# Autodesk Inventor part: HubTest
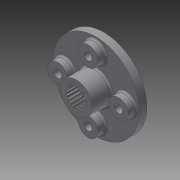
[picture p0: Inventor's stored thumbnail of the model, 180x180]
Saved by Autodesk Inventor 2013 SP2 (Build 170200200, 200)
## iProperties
Created: 2020-02
Part Number: HubTest
Material: Generic
Document SubType Name: Modeling
Designer: DELL
Density: 1 g/cm^3
Author: DELL
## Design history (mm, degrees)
sketch "Sketch1" dims "d2" = 4.61623
  geometry: C1 r 4 at (0, 0); C2 r 2.6 at (0, 0); A1 r 2.308 centre (0, 0) between (0.414, 2.271) and (0.308, 2.287); A2 r 1.037 centre (-0.708, 1.95) between (0.259, 2.327) and (0.255, 2.336); A3 r 0.063 centre (0.317, 2.349) between (0.259, 2.327) and (0.308, 2.287); A4 r 0.062 centre (0.425, 2.332) between (0.414, 2.271) and (0.473, 2.293); A5 r 1.037 centre (1.276, 1.636) between (0.48, 2.301) and (0.473, 2.293); A6 r 1.037 centre (1.276, 1.636) between (0.706, 2.502) and (0.473, 2.293); A7 r 2.6 centre (0, 0) between (0.706, 2.502) and (0.102, 2.598); 2 further points
  constraints: 14 point on circle, 9 centre point, 5 coincident, 6 other
  dimensions: "d3" = 8 diameter of C1; "d8" = 5.2 diameter of C2
extrude "Extrusion1" new body sketch "Sketch1" distance "d4" = 5; taper "d5" = 0 deg
sketch "Sketch5"
  geometry: C1 r 2.6 at (0, 0) reference; 1 further point
extrude "Extrusion4" join sketch "Sketch5" distance "d32" = 1.5; taper "d33" = 0 deg
sketch "Sketch2"
  geometry: L1 (0, -5.6)-(0, 5.6) reference; A1 r 2.6 centre (0, 0) between (0.306, 2.582) and (-0.306, 2.582); A2 r 0.063 centre (-0.055, 2.37) between (-0.108, 2.338) and (-0.053, 2.308); A3 r 0.062 centre (0.055, 2.37) between (0.053, 2.308) and (0.108, 2.338); A4 r 2.308 centre (0, 0) between (0.053, 2.308) and (-0.053, 2.308); A5 r 1.126 centre (1.074, 1.759) between (0.306, 2.582) and (0.108, 2.338); A6 r 1.126 centre (-1.074, 1.759) between (-0.108, 2.338) and (-0.306, 2.582); 1 further point
  constraints: 12 point on circle, 6 centre point, 2 coincident, 1 horizontal alignment, 1 symmetric about line, 1 other
  dimensions: "d9" = 2.6 radius of A1; "d10" = 2.30812 radius of A4; "d11" = 0.0625 radius of A2; "d12" = 0.0625 radius of A3; "d13" = 0.05465 distance from line of A2.centre L1; "d14" = 0.05465 distance from line of L1 A3.centre; "d15" = 2.36999 vertical distance of A2.centre point (0, 0); "d16" = 1.75901 vertical distance of A5.centre point (0, 0); "d17" = 1.07399 horizontal distance of A5.centre point (0, 0); "d18" = 1.12592 radius of A5
extrude "Extrusion2" join sketch "Sketch2" distance "d19" = 3.25; taper "d20" = 0 deg
sketch "Sketch3"
  geometry: C1 r 11 at (0, 0); 1 further point
  constraints: 1 centre point, 1 coincident
  dimensions: "d21" = 22 diameter of C1
extrude "Extrusion3" join sketch "Sketch3" distance "d23" = 2; taper "d24" = 0 deg
sketch "Sketch4"
  geometry: 2 further points
  constraints: 1 coincident
hole "Hole1" sketch "Sketch4" at (0, 0) diameter "d25" = 2.8; stored, may be unused: countersink angle "d29" = 90 deg, drill point angle "d31" = 0 deg; dims "d26" = 6, "d27" = 5, "d28" = 1.75, "d30" = 4
sketch "Sketch6" dims "d37" = 15.5
  geometry: C1 r 2.5 at (7.75, 0); 2 further points
  constraints: 2 horizontal alignment, 1 centre point, 1 coincident, 2 other
  dimensions: "d39" = 5 diameter of C1
extrude "Extrusion5" join sketch "Sketch6" distance "d40" = 2; taper "d41" = 0 deg
sketch "Sketch7"
  geometry: C1 r 2.5 at (0, 0) reference; 2 further points
  constraints: 1 coincident
hole "Hole2" sketch "Sketch7" at (0, 0) diameter "d42" = 2; stored, may be unused: countersink angle "d46" = 90 deg, drill point angle "d48" = 118 deg; dims "d43" = 6, "d44" = 6.5, "d45" = 1, "d47" = 2
pattern_circular "Circular Pattern2" dims angle "d50" = 360 deg
fillet "Fillet1" dims "d52" = 0.5
body "Solid1"
pattern_circular "Circular Pattern1" dims angle "d35" = 360 deg
